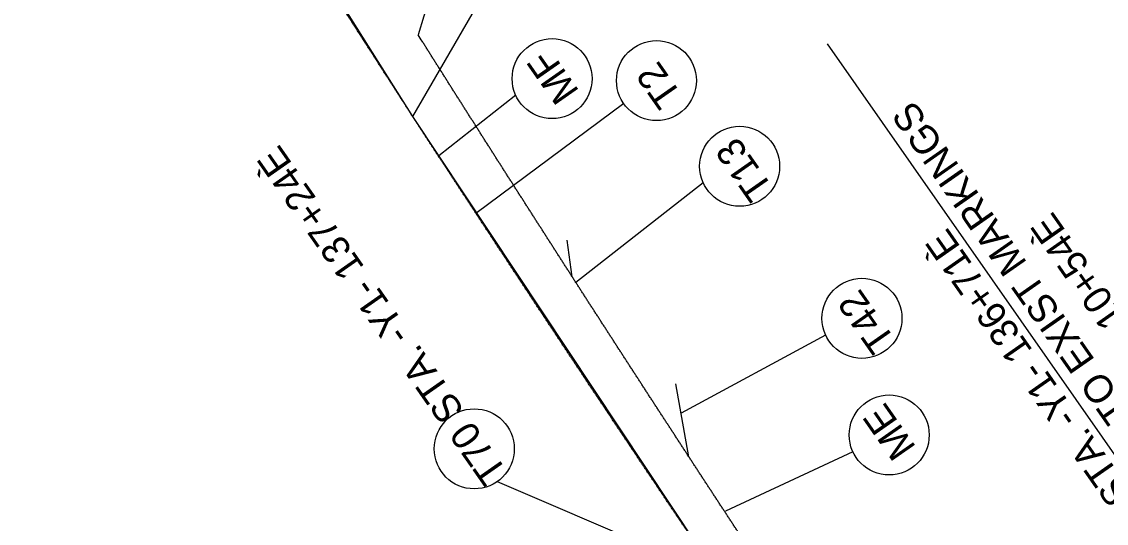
# Model space of a CAD drawing. Extents: x 1487421 to 1489048, y 497792 to 499463.
# Drawn here: x 1487485 to 1487756.3, y 498471.4 to 498596.8 of the extents above; entities that cross this region are included whole.
import ezdxf

# ---------------------------------------------------------------- set-up
doc = ezdxf.new("R2010")
doc.units = 0
for name, color, linetype in [('Prop Mkg 3ft Min Skp 9ft White', 7, 'Continuous'), ('Prop Mkg Solid Double Yellow', 7, 'Continuous'), ('Prop Mkg Solid White Lane Line', 7, 'Continuous'), ('Prop Mkg Solid Yellow Diagonals', 7, 'Continuous'), ('Prop Mkr CR 80ft Spc', 7, 'Continuous'), ('Prop Mkr Yel 20ft Spc', 7, 'Continuous'), ('Text', 7, 'Continuous')]:
    doc.layers.add(name, color=color, linetype=linetype)

msp = doc.modelspace()

# ---------------------------------------------------------------- linework, layer by layer
at = {"layer": 'Prop Mkg 3ft Min Skp 9ft White'}
msp.add_spline([(1487582.81, 498573.14), (1487582.36, 498573.83), (1487581.92, 498574.52), (1487581.47, 498575.22), (1487581.02, 498575.91), (1487580.57, 498576.6), (1487580.12, 498577.3), (1487579.67, 498577.99), (1487579.23, 498578.69), (1487578.78, 498579.38), (1487578.33, 498580.07), (1487577.88, 498580.77), (1487577.44, 498581.46), (1487576.99, 498582.16), (1487576.54, 498582.85), (1487576.09, 498583.55), (1487575.64, 498584.24), (1487575.2, 498584.93), (1487574.75, 498585.63), (1487574.3, 498586.32), (1487573.86, 498587.02), (1487573.41, 498587.71), (1487572.96, 498588.41), (1487572.51, 498589.1), (1487572.07, 498589.8), (1487571.62, 498590.49), (1487571.17, 498591.18), (1487570.73, 498591.88), (1487570.28, 498592.57), (1487569.83, 498593.27), (1487569.39, 498593.96), (1487568.94, 498594.66), (1487568.5, 498595.35), (1487568.05, 498596.05), (1487567.6, 498596.74), (1487567.16, 498597.44), (1487566.71, 498598.13), (1487566.27, 498598.83), (1487565.82, 498599.52), (1487565.37, 498600.22), (1487564.93, 498600.92), (1487564.48, 498601.61), (1487564.04, 498602.31), (1487563.59, 498603), (1487563.15, 498603.7), (1487562.7, 498604.39), (1487562.26, 498605.09), (1487561.81, 498605.78), (1487561.36, 498606.48), (1487560.92, 498607.18), (1487560.47, 498607.87), (1487560.03, 498608.57), (1487559.59, 498609.26), (1487559.14, 498609.96), (1487558.7, 498610.65), (1487558.25, 498611.35), (1487557.81, 498612.05), (1487557.36, 498612.74), (1487556.92, 498613.44), (1487556.47, 498614.14), (1487556.03, 498614.83), (1487555.59, 498615.53), (1487555.14, 498616.22), (1487554.7, 498616.92), (1487554.25, 498617.62), (1487553.81, 498618.31), (1487553.37, 498619.01), (1487552.92, 498619.71), (1487552.48, 498620.4), (1487552.03, 498621.1), (1487551.59, 498621.8), (1487551.15, 498622.49), (1487550.7, 498623.19), (1487550.26, 498623.89), (1487549.82, 498624.58)], degree=3, dxfattribs=at)
at = {"layer": 'Prop Mkg Solid Double Yellow'}
for points in [[(1487621.72, 498534.62), (1487621.21, 498535.41), (1487620.7, 498536.2), (1487620.19, 498537), (1487619.68, 498537.79), (1487619.17, 498538.59), (1487618.66, 498539.38), (1487618.15, 498540.17), (1487617.64, 498540.97), (1487617.13, 498541.76), (1487616.62, 498542.56), (1487616.11, 498543.35), (1487615.6, 498544.15), (1487615.09, 498544.94), (1487614.58, 498545.74), (1487614.07, 498546.53), (1487613.56, 498547.32), (1487613.05, 498548.12), (1487612.55, 498548.91), (1487612.04, 498549.71), (1487611.53, 498550.5), (1487611.02, 498551.3), (1487610.51, 498552.09), (1487610, 498552.89), (1487609.49, 498553.68), (1487608.99, 498554.48), (1487608.48, 498555.27), (1487607.97, 498556.07), (1487607.46, 498556.87), (1487606.95, 498557.66), (1487606.45, 498558.46), (1487605.94, 498559.25), (1487605.43, 498560.05), (1487604.92, 498560.84), (1487604.41, 498561.64), (1487603.91, 498562.43), (1487603.4, 498563.23), (1487602.89, 498564.03), (1487602.39, 498564.82), (1487601.88, 498565.62), (1487601.37, 498566.41), (1487600.87, 498567.21), (1487600.36, 498568.01), (1487599.85, 498568.8), (1487599.35, 498569.6), (1487598.84, 498570.4), (1487598.33, 498571.19), (1487597.83, 498571.99), (1487597.32, 498572.78), (1487596.82, 498573.58), (1487596.31, 498574.38), (1487595.8, 498575.17), (1487595.3, 498575.97), (1487594.79, 498576.77), (1487594.29, 498577.56), (1487593.78, 498578.36), (1487593.28, 498579.16), (1487592.77, 498579.96), (1487592.27, 498580.75), (1487591.76, 498581.55), (1487591.26, 498582.35), (1487590.75, 498583.14), (1487590.25, 498583.94), (1487589.74, 498584.74), (1487589.24, 498585.54), (1487588.73, 498586.33), (1487588.23, 498587.13), (1487587.72, 498587.93), (1487587.22, 498588.73), (1487586.72, 498589.52), (1487586.21, 498590.32), (1487585.71, 498591.12), (1487585.2, 498591.92), (1487584.2, 498593.51)], [(1487659.77, 498476.03), (1487659.25, 498476.82), (1487658.74, 498477.61), (1487658.22, 498478.4), (1487657.7, 498479.19), (1487657.18, 498479.98), (1487656.67, 498480.77), (1487656.15, 498481.56), (1487655.63, 498482.35), (1487655.12, 498483.14), (1487654.6, 498483.93), (1487654.08, 498484.72), (1487653.57, 498485.51), (1487653.05, 498486.3), (1487652.53, 498487.09), (1487652.02, 498487.88), (1487651.5, 498488.67), (1487650.98, 498489.46), (1487650.47, 498490.25), (1487649.95, 498491.04), (1487649.44, 498491.83), (1487648.92, 498492.62), (1487648.41, 498493.42), (1487647.89, 498494.21), (1487647.37, 498495), (1487646.86, 498495.79), (1487646.34, 498496.58), (1487645.83, 498497.37), (1487645.31, 498498.16), (1487644.8, 498498.95), (1487644.28, 498499.74), (1487643.77, 498500.54), (1487643.25, 498501.33), (1487642.74, 498502.12), (1487642.22, 498502.91), (1487641.71, 498503.7), (1487641.2, 498504.49), (1487640.68, 498505.28), (1487640.17, 498506.08), (1487639.65, 498506.87), (1487639.14, 498507.66), (1487638.63, 498508.45), (1487638.11, 498509.24), (1487637.6, 498510.04), (1487637.08, 498510.83), (1487636.57, 498511.62), (1487636.06, 498512.41), (1487635.54, 498513.2), (1487635.03, 498514), (1487634.52, 498514.79), (1487634, 498515.58), (1487633.49, 498516.37), (1487632.98, 498517.17), (1487632.47, 498517.96), (1487631.95, 498518.75), (1487631.44, 498519.54), (1487630.93, 498520.34), (1487630.42, 498521.13), (1487629.9, 498521.92), (1487629.39, 498522.72), (1487628.88, 498523.51), (1487628.37, 498524.3), (1487627.86, 498525.09), (1487627.34, 498525.89), (1487626.83, 498526.68), (1487626.32, 498527.47), (1487625.81, 498528.27), (1487625.3, 498529.06), (1487624.79, 498529.85), (1487624.28, 498530.65), (1487623.76, 498531.44), (1487623.25, 498532.24), (1487622.74, 498533.03), (1487622.23, 498533.82), (1487621.72, 498534.62)], [(1487698.35, 498417.76), (1487697.82, 498418.54), (1487697.3, 498419.33), (1487696.77, 498420.12), (1487696.25, 498420.9), (1487695.72, 498421.69), (1487695.2, 498422.47), (1487694.68, 498423.26), (1487694.15, 498424.04), (1487693.63, 498424.83), (1487693.1, 498425.62), (1487692.58, 498426.4), (1487692.06, 498427.19), (1487691.53, 498427.97), (1487691.01, 498428.76), (1487690.49, 498429.55), (1487689.96, 498430.33), (1487689.44, 498431.12), (1487688.92, 498431.9), (1487688.39, 498432.69), (1487687.87, 498433.48), (1487687.35, 498434.26), (1487686.82, 498435.05), (1487686.3, 498435.84), (1487685.78, 498436.62), (1487685.26, 498437.41), (1487684.73, 498438.2), (1487684.21, 498438.98), (1487683.69, 498439.77), (1487683.17, 498440.56), (1487682.65, 498441.34), (1487682.12, 498442.13), (1487681.6, 498442.92), (1487681.08, 498443.71), (1487680.56, 498444.49), (1487680.04, 498445.28), (1487679.52, 498446.07), (1487678.99, 498446.86), (1487678.47, 498447.64), (1487677.95, 498448.43), (1487677.43, 498449.22), (1487676.91, 498450.01), (1487676.39, 498450.79), (1487675.87, 498451.58), (1487675.35, 498452.37), (1487674.83, 498453.16), (1487674.31, 498453.94), (1487673.79, 498454.73), (1487673.27, 498455.52), (1487672.75, 498456.31), (1487672.23, 498457.1), (1487671.71, 498457.88), (1487671.19, 498458.67), (1487670.67, 498459.46), (1487670.15, 498460.25), (1487669.63, 498461.04), (1487669.11, 498461.83), (1487668.59, 498462.62), (1487668.07, 498463.4), (1487667.55, 498464.19), (1487667.03, 498464.98), (1487666.51, 498465.77), (1487665.99, 498466.56), (1487665.47, 498467.35), (1487664.95, 498468.14), (1487664.44, 498468.93), (1487663.92, 498469.72), (1487663.4, 498470.5), (1487662.88, 498471.29), (1487662.36, 498472.08), (1487661.84, 498472.87), (1487661.33, 498473.66), (1487660.81, 498474.45), (1487660.29, 498475.24), (1487659.77, 498476.03)]]:
    msp.add_spline(points, degree=3, dxfattribs=at)
at = {"layer": 'Prop Mkg Solid White Lane Line'}
for points in [[(1487587.99, 498565.2), (1487587.51, 498565.94), (1487587.02, 498566.68), (1487586.54, 498567.42), (1487586.06, 498568.16), (1487585.58, 498568.89), (1487585.1, 498569.63), (1487584.61, 498570.37), (1487584.13, 498571.11), (1487583.65, 498571.85), (1487583.17, 498572.59), (1487582.81, 498573.14)], [(1487623.91, 498510.67), (1487623.42, 498511.4), (1487622.94, 498512.14), (1487622.45, 498512.87), (1487621.96, 498513.61), (1487621.47, 498514.34), (1487620.98, 498515.08), (1487620.49, 498515.81), (1487620.01, 498516.55), (1487619.52, 498517.29), (1487619.03, 498518.02), (1487618.54, 498518.76), (1487618.06, 498519.49), (1487617.57, 498520.23), (1487617.08, 498520.96), (1487616.59, 498521.7), (1487616.11, 498522.43), (1487615.62, 498523.17), (1487615.13, 498523.91), (1487614.65, 498524.64), (1487614.16, 498525.38), (1487613.67, 498526.11), (1487613.18, 498526.85), (1487612.7, 498527.59), (1487612.21, 498528.32), (1487611.73, 498529.06), (1487611.24, 498529.8), (1487610.75, 498530.53), (1487610.27, 498531.27), (1487609.78, 498532.01), (1487609.29, 498532.74), (1487608.81, 498533.48), (1487608.32, 498534.21), (1487607.84, 498534.95), (1487607.35, 498535.69), (1487606.86, 498536.43), (1487606.38, 498537.16), (1487605.89, 498537.9), (1487605.41, 498538.64), (1487604.92, 498539.37), (1487604.44, 498540.11), (1487603.95, 498540.85), (1487603.47, 498541.58), (1487602.98, 498542.32), (1487602.5, 498543.06), (1487602.01, 498543.8), (1487601.53, 498544.53), (1487601.04, 498545.27), (1487600.56, 498546.01), (1487600.07, 498546.75), (1487599.59, 498547.48), (1487599.11, 498548.22), (1487598.62, 498548.96), (1487598.14, 498549.7), (1487597.65, 498550.43), (1487597.17, 498551.17), (1487596.68, 498551.91), (1487596.2, 498552.65), (1487595.72, 498553.39), (1487595.23, 498554.12), (1487594.75, 498554.86), (1487594.27, 498555.6), (1487593.78, 498556.34), (1487593.3, 498557.08), (1487592.82, 498557.81), (1487592.33, 498558.55), (1487591.85, 498559.29), (1487591.37, 498560.03), (1487590.88, 498560.77), (1487590.4, 498561.51), (1487589.92, 498562.25), (1487589.44, 498562.98), (1487588.95, 498563.72), (1487588.47, 498564.46), (1487587.99, 498565.2)], [(1487637.91, 498489.68), (1487637.62, 498490.11), (1487637.13, 498490.84), (1487636.64, 498491.58), (1487636.15, 498492.31), (1487635.66, 498493.04), (1487635.17, 498493.78), (1487634.68, 498494.51), (1487634.19, 498495.24), (1487633.7, 498495.98), (1487633.21, 498496.71), (1487632.72, 498497.45), (1487632.23, 498498.18), (1487631.74, 498498.91), (1487631.25, 498499.65), (1487630.76, 498500.38), (1487630.27, 498501.12), (1487629.78, 498501.85), (1487629.29, 498502.59), (1487628.8, 498503.32), (1487628.31, 498504.05), (1487627.82, 498504.79), (1487627.33, 498505.52), (1487626.84, 498506.26), (1487626.36, 498506.99), (1487625.87, 498507.73), (1487625.38, 498508.46), (1487624.89, 498509.2), (1487624.4, 498509.93), (1487623.91, 498510.67)], [(1487660.29, 498456.42), (1487659.79, 498457.15), (1487659.3, 498457.88), (1487658.8, 498458.61), (1487658.31, 498459.34), (1487657.82, 498460.08), (1487657.32, 498460.81), (1487656.83, 498461.54), (1487656.33, 498462.27), (1487655.84, 498463), (1487655.35, 498463.73), (1487654.85, 498464.47), (1487654.36, 498465.2), (1487653.87, 498465.93), (1487653.37, 498466.66), (1487652.88, 498467.39), (1487652.39, 498468.12), (1487651.89, 498468.86), (1487651.4, 498469.59), (1487650.91, 498470.32), (1487650.41, 498471.05), (1487649.92, 498471.79), (1487649.43, 498472.52), (1487648.93, 498473.25), (1487648.44, 498473.98), (1487647.95, 498474.71), (1487647.46, 498475.45), (1487646.96, 498476.18), (1487646.47, 498476.91), (1487645.98, 498477.64), (1487645.49, 498478.38), (1487644.99, 498479.11), (1487644.5, 498479.84), (1487644.01, 498480.58), (1487643.52, 498481.31), (1487643.03, 498482.04), (1487642.54, 498482.77), (1487642.04, 498483.51), (1487641.55, 498484.24), (1487641.06, 498484.97), (1487640.57, 498485.71), (1487640.08, 498486.44), (1487639.59, 498487.17), (1487639.1, 498487.91), (1487638.61, 498488.64), (1487638.11, 498489.37), (1487637.91, 498489.68)]]:
    msp.add_spline(points, degree=3, dxfattribs=at)
at = {"layer": 'Prop Mkg Solid Yellow Diagonals'}
for p, q in [((1487622.75, 498533.02), (1487621.44, 498542.16)), ((1487651.92, 498488.03), (1487648.68, 498506.32))]:
    msp.add_line(p, q, dxfattribs=at)
at = {"layer": 'Prop Mkr CR 80ft Spc'}
msp.add_line((1487485.03, 498728.19), (1487582.81, 498573.14), dxfattribs=at)
msp.add_lwpolyline([(1487582.81, 498573.14), (1487660.29, 498456.42), (1487697.11, 498402.46), (1487706.98, 498388.89)], dxfattribs=at)
at = {"layer": 'Prop Mkr Yel 20ft Spc'}
for points in [[(1487621.72, 498534.62), (1487621.21, 498535.41), (1487620.7, 498536.2), (1487620.19, 498537), (1487619.68, 498537.79), (1487619.17, 498538.59), (1487618.66, 498539.38), (1487618.15, 498540.17), (1487617.64, 498540.97), (1487617.13, 498541.76), (1487616.62, 498542.56), (1487616.11, 498543.35), (1487615.6, 498544.15), (1487615.09, 498544.94), (1487614.58, 498545.74), (1487614.07, 498546.53), (1487613.56, 498547.32), (1487613.05, 498548.12), (1487612.55, 498548.91), (1487612.04, 498549.71), (1487611.53, 498550.5), (1487611.02, 498551.3), (1487610.51, 498552.09), (1487610, 498552.89), (1487609.49, 498553.68), (1487608.99, 498554.48), (1487608.48, 498555.27), (1487607.97, 498556.07), (1487607.46, 498556.87), (1487606.95, 498557.66), (1487606.45, 498558.46), (1487605.94, 498559.25), (1487605.43, 498560.05), (1487604.92, 498560.84), (1487604.41, 498561.64), (1487603.91, 498562.43), (1487603.4, 498563.23), (1487602.89, 498564.03), (1487602.39, 498564.82), (1487601.88, 498565.62), (1487601.37, 498566.41), (1487600.87, 498567.21), (1487600.36, 498568.01), (1487599.85, 498568.8), (1487599.35, 498569.6), (1487598.84, 498570.4), (1487598.33, 498571.19), (1487597.83, 498571.99), (1487597.32, 498572.78), (1487596.82, 498573.58), (1487596.31, 498574.38), (1487595.8, 498575.17), (1487595.3, 498575.97), (1487594.79, 498576.77), (1487594.29, 498577.56), (1487593.78, 498578.36), (1487593.28, 498579.16), (1487592.77, 498579.96), (1487592.27, 498580.75), (1487591.76, 498581.55), (1487591.26, 498582.35), (1487590.75, 498583.14), (1487590.25, 498583.94), (1487589.74, 498584.74), (1487589.24, 498585.54), (1487588.73, 498586.33), (1487588.23, 498587.13), (1487587.72, 498587.93), (1487587.22, 498588.73), (1487586.72, 498589.52), (1487586.21, 498590.32), (1487585.71, 498591.12), (1487585.2, 498591.92), (1487584.2, 498593.51)], [(1487659.77, 498476.03), (1487659.25, 498476.82), (1487658.74, 498477.61), (1487658.22, 498478.4), (1487657.7, 498479.19), (1487657.18, 498479.98), (1487656.67, 498480.77), (1487656.15, 498481.56), (1487655.63, 498482.35), (1487655.12, 498483.14), (1487654.6, 498483.93), (1487654.08, 498484.72), (1487653.57, 498485.51), (1487653.05, 498486.3), (1487652.53, 498487.09), (1487652.02, 498487.88), (1487651.5, 498488.67), (1487650.98, 498489.46), (1487650.47, 498490.25), (1487649.95, 498491.04), (1487649.44, 498491.83), (1487648.92, 498492.62), (1487648.41, 498493.42), (1487647.89, 498494.21), (1487647.37, 498495), (1487646.86, 498495.79), (1487646.34, 498496.58), (1487645.83, 498497.37), (1487645.31, 498498.16), (1487644.8, 498498.95), (1487644.28, 498499.74), (1487643.77, 498500.54), (1487643.25, 498501.33), (1487642.74, 498502.12), (1487642.22, 498502.91), (1487641.71, 498503.7), (1487641.2, 498504.49), (1487640.68, 498505.28), (1487640.17, 498506.08), (1487639.65, 498506.87), (1487639.14, 498507.66), (1487638.63, 498508.45), (1487638.11, 498509.24), (1487637.6, 498510.04), (1487637.08, 498510.83), (1487636.57, 498511.62), (1487636.06, 498512.41), (1487635.54, 498513.2), (1487635.03, 498514), (1487634.52, 498514.79), (1487634, 498515.58), (1487633.49, 498516.37), (1487632.98, 498517.17), (1487632.47, 498517.96), (1487631.95, 498518.75), (1487631.44, 498519.54), (1487630.93, 498520.34), (1487630.42, 498521.13), (1487629.9, 498521.92), (1487629.39, 498522.72), (1487628.88, 498523.51), (1487628.37, 498524.3), (1487627.86, 498525.09), (1487627.34, 498525.89), (1487626.83, 498526.68), (1487626.32, 498527.47), (1487625.81, 498528.27), (1487625.3, 498529.06), (1487624.79, 498529.85), (1487624.28, 498530.65), (1487623.76, 498531.44), (1487623.25, 498532.24), (1487622.74, 498533.03), (1487622.23, 498533.82), (1487621.72, 498534.62)], [(1487698.35, 498417.76), (1487697.82, 498418.54), (1487697.3, 498419.33), (1487696.77, 498420.12), (1487696.25, 498420.9), (1487695.72, 498421.69), (1487695.2, 498422.47), (1487694.68, 498423.26), (1487694.15, 498424.04), (1487693.63, 498424.83), (1487693.1, 498425.62), (1487692.58, 498426.4), (1487692.06, 498427.19), (1487691.53, 498427.97), (1487691.01, 498428.76), (1487690.49, 498429.55), (1487689.96, 498430.33), (1487689.44, 498431.12), (1487688.92, 498431.9), (1487688.39, 498432.69), (1487687.87, 498433.48), (1487687.35, 498434.26), (1487686.82, 498435.05), (1487686.3, 498435.84), (1487685.78, 498436.62), (1487685.26, 498437.41), (1487684.73, 498438.2), (1487684.21, 498438.98), (1487683.69, 498439.77), (1487683.17, 498440.56), (1487682.65, 498441.34), (1487682.12, 498442.13), (1487681.6, 498442.92), (1487681.08, 498443.71), (1487680.56, 498444.49), (1487680.04, 498445.28), (1487679.52, 498446.07), (1487678.99, 498446.86), (1487678.47, 498447.64), (1487677.95, 498448.43), (1487677.43, 498449.22), (1487676.91, 498450.01), (1487676.39, 498450.79), (1487675.87, 498451.58), (1487675.35, 498452.37), (1487674.83, 498453.16), (1487674.31, 498453.94), (1487673.79, 498454.73), (1487673.27, 498455.52), (1487672.75, 498456.31), (1487672.23, 498457.1), (1487671.71, 498457.88), (1487671.19, 498458.67), (1487670.67, 498459.46), (1487670.15, 498460.25), (1487669.63, 498461.04), (1487669.11, 498461.83), (1487668.59, 498462.62), (1487668.07, 498463.4), (1487667.55, 498464.19), (1487667.03, 498464.98), (1487666.51, 498465.77), (1487665.99, 498466.56), (1487665.47, 498467.35), (1487664.95, 498468.14), (1487664.44, 498468.93), (1487663.92, 498469.72), (1487663.4, 498470.5), (1487662.88, 498471.29), (1487662.36, 498472.08), (1487661.84, 498472.87), (1487661.33, 498473.66), (1487660.81, 498474.45), (1487660.29, 498475.24), (1487659.77, 498476.03)]]:
    msp.add_spline(points, degree=3, dxfattribs=at)
at = {"layer": 'Text'}
for p, q in [((1487641.56, 498674.53), (1487582.81, 498573.14)), ((1487597.46, 498638.13), (1487584.2, 498593.51)), ((1487686.51, 498591.29), (1487764.84, 498479.24)), ((1487608.61, 498578.41), (1487589.39, 498563.3)), ((1487635.62, 498576.33), (1487598.66, 498548.9)), ((1487655.51, 498556.5), (1487623.65, 498531.62)), ((1487686.09, 498518.49), (1487649.98, 498498.99)), ((1487692.91, 498489.32), (1487661.07, 498474.5)), ((1487603.98, 498481.86), (1487662.32, 498456.94))]:
    msp.add_line(p, q, dxfattribs=at)
for centre in [(1487617.7, 498582.58), (1487643.8, 498582.09), (1487664.6, 498560.67), (1487695.18, 498522.66), (1487702, 498493.5), (1487598.22, 498490.04)]:
    msp.add_circle(centre, 10, dxfattribs=at)

# ---------------------------------------------------------------- texts
for s, rotation, p in [('MF', 124.9556, (1487624.63, 498579.4)), ('T2', 124.9556, (1487650.37, 498578.37)), ('TIE TO EXIST MARKINGS', 124.9554, (1487772.41, 498485.32)), ('T70 STA. -Y1- 137+24È', 124.9556, (1487606.68, 498484.26)), ('T13', 124.9556, (1487673.16, 498555.17)), ('T61 STA. -L- 10+54È', 124.9556, (1487793.56, 498476.88)), ('STA. -Y1- 136+71È', 124.9554, (1487763.09, 498478.8)), ('T42', 124.9556, (1487703.76, 498517.13)), ('ME', 124.9556, (1487708.87, 498490.41))]:
    msp.add_text(s, height=7, rotation=rotation, dxfattribs=at).set_placement(p)

doc.saveas('drawing.dxf')
